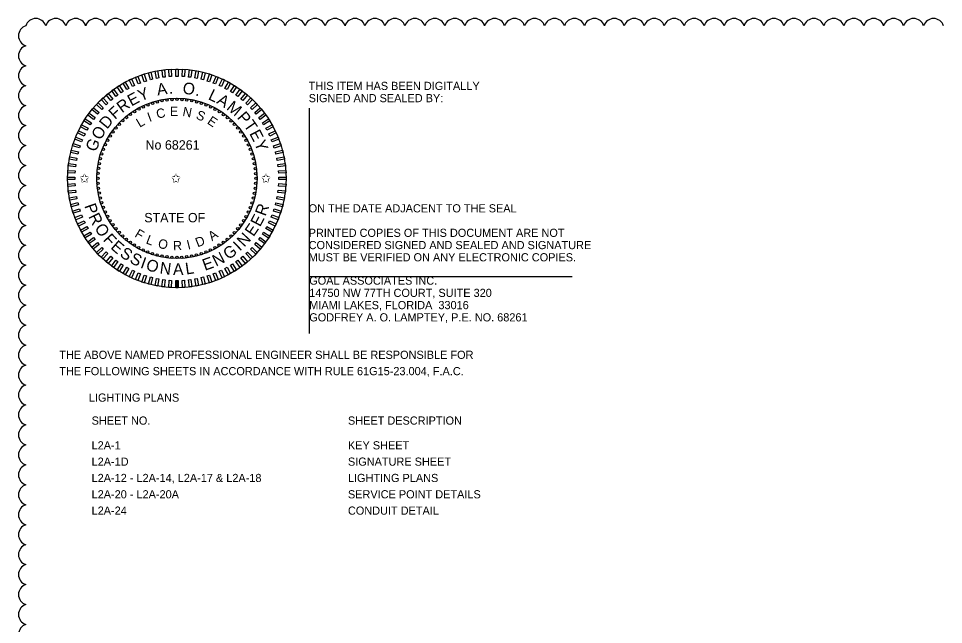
# Model space of a CAD drawing. Extents: x -811 to -790, y -2284 to -2178.
# Drawn here: x -810.85 to -802.91, y -2240.21 to -2235.02 of the extents above; entities that cross this region are included whole.
import ezdxf

# ---------------------------------------------------------------- set-up
doc = ezdxf.new("R2010")
doc.units = 0
for name, color, linetype in [('AdhocPoint_dp', 7, 'Continuous'), ('PlotBorder_dp', 7, 'Continuous'), ('TextMinor', 7, 'Continuous'), ('TextMisc', 7, 'Continuous'), ('TextShtNo', 7, 'Continuous'), ('TextTitle', 7, 'Continuous')]:
    doc.layers.add(name, color=color, linetype=linetype)

msp = doc.modelspace()

# ---------------------------------------------------------------- linework, layer by layer
at = {"layer": 'AdhocPoint_dp'}
for p, q in [((-808.3546, -2235.7843), (-808.3546, -2237.719)), ((-808.3546, -2237.229), (-806.0979, -2237.229))]:
    msp.add_line(p, q, dxfattribs=at)
at = {"layer": 'TextMinor'}
for radius in [0.9375, 0.6875]:
    msp.add_circle((-809.4901, -2236.3877), radius, dxfattribs=at)
at = {"layer": 'TextShtNo'}
for p, q in [((-809.5001, -2237.3253), (-809.5003, -2237.2628)), ((-809.4901, -2237.3252), (-809.4903, -2237.2627)), ((-809.4801, -2237.3252), (-809.4803, -2237.2627))]:
    msp.add_line(p, q, dxfattribs=at)
for points in [[(-809.7508, -2235.5524), (-809.77, -2235.5586), (-809.7893, -2235.4992), (-809.7701, -2235.493)], [(-809.6979, -2235.5377), (-809.7174, -2235.5427), (-809.7329, -2235.4822), (-809.7134, -2235.4772)], [(-809.6441, -2235.5263), (-809.6639, -2235.5301), (-809.6756, -2235.4688), (-809.6558, -2235.465)], [(-809.5897, -2235.5183), (-809.6097, -2235.5209), (-809.6175, -2235.4589), (-809.5975, -2235.4564)], [(-809.5349, -2235.5138), (-809.555, -2235.5151), (-809.559, -2235.4527), (-809.5388, -2235.4515)], [(-809.4799, -2235.5127), (-809.5001, -2235.5127), (-809.5001, -2235.4503), (-809.4799, -2235.4503)], [(-809.425, -2235.5151), (-809.4452, -2235.5138), (-809.4412, -2235.4515), (-809.4211, -2235.4528)], [(-809.3703, -2235.5209), (-809.3904, -2235.5184), (-809.3825, -2235.4564), (-809.3625, -2235.4589)], [(-809.3162, -2235.5301), (-809.336, -2235.5263), (-809.3243, -2235.465), (-809.3045, -2235.4688)], [(-809.2626, -2235.5427), (-809.2822, -2235.5377), (-809.2667, -2235.4772), (-809.2471, -2235.4823)], [(-809.21, -2235.5587), (-809.2292, -2235.5524), (-809.2099, -2235.4931), (-809.1907, -2235.4993)], [(-809.9027, -2235.616), (-809.9204, -2235.6258), (-809.9505, -2235.571), (-809.9328, -2235.5613)], [(-809.8535, -2235.5917), (-809.8717, -2235.6002), (-809.8983, -2235.5438), (-809.8801, -2235.5352)], [(-809.8028, -2235.5704), (-809.8215, -2235.5778), (-809.8445, -2235.5198), (-809.8258, -2235.5124)], [(-809.1585, -2235.5779), (-809.1773, -2235.5705), (-809.1543, -2235.5124), (-809.1355, -2235.5199)], [(-809.1083, -2235.6003), (-809.1266, -2235.5917), (-809.1, -2235.5352), (-809.0817, -2235.5438)], [(-809.0596, -2235.6259), (-809.0773, -2235.6161), (-809.0473, -2235.5614), (-809.0296, -2235.5711)], [(-810.04, -2235.707), (-810.0556, -2235.7199), (-810.0954, -2235.6718), (-810.0798, -2235.6589)], [(-809.9962, -2235.6738), (-810.0125, -2235.6857), (-810.0492, -2235.6352), (-810.0329, -2235.6233)], [(-809.9504, -2235.6435), (-809.9674, -2235.6543), (-810.0009, -2235.6016), (-809.9838, -2235.5908)], [(-809.0127, -2235.6544), (-809.0297, -2235.6436), (-808.9962, -2235.5909), (-808.9792, -2235.6017)], [(-808.9676, -2235.6858), (-808.9839, -2235.674), (-808.9472, -2235.6234), (-808.9308, -2235.6353)], [(-808.9245, -2235.72), (-808.9401, -2235.7071), (-808.9003, -2235.659), (-808.8847, -2235.6719)], [(-810.121, -2235.7813), (-810.1348, -2235.796), (-810.1804, -2235.7533), (-810.1665, -2235.7386)], [(-810.0817, -2235.7429), (-810.0964, -2235.7567), (-810.1392, -2235.7112), (-810.1244, -2235.6974)], [(-808.8837, -2235.7568), (-808.8984, -2235.743), (-808.8557, -2235.6975), (-808.841, -2235.7113)], [(-808.8453, -2235.7962), (-808.8591, -2235.7815), (-808.8136, -2235.7387), (-808.7998, -2235.7534)], [(-810.1579, -2235.8221), (-810.1707, -2235.8377), (-810.2188, -2235.7979), (-810.206, -2235.7823)], [(-808.8094, -2235.8378), (-808.8223, -2235.8223), (-808.7742, -2235.7825), (-808.7613, -2235.798)], [(-810.2235, -2235.9103), (-810.2343, -2235.9273), (-810.287, -2235.8939), (-810.2762, -2235.8768)], [(-810.192, -2235.8652), (-810.2039, -2235.8815), (-810.2544, -2235.8448), (-810.2426, -2235.8285)], [(-808.7762, -2235.8817), (-808.7881, -2235.8653), (-808.7376, -2235.8286), (-808.7257, -2235.845)], [(-808.7459, -2235.9275), (-808.7567, -2235.9104), (-808.7039, -2235.877), (-808.6931, -2235.894)], [(-810.2775, -2236.006), (-810.2861, -2236.0242), (-810.3426, -2235.9976), (-810.334, -2235.9794)], [(-810.252, -2235.9573), (-810.2617, -2235.975), (-810.3164, -2235.9449), (-810.3067, -2235.9272)], [(-808.7184, -2235.9751), (-808.7281, -2235.9574), (-808.6734, -2235.9273), (-808.6637, -2235.945)], [(-808.694, -2236.0244), (-808.7026, -2236.0061), (-808.6461, -2235.9795), (-808.6375, -2235.9978)], [(-810.3, -2236.0562), (-810.3074, -2236.0749), (-810.3654, -2236.0519), (-810.358, -2236.0332)], [(-808.6728, -2236.0751), (-808.6802, -2236.0563), (-808.6222, -2236.0333), (-808.6147, -2236.0521)], [(-810.3192, -2236.1077), (-810.3254, -2236.1269), (-810.3848, -2236.1076), (-810.3786, -2236.0884)], [(-808.6548, -2236.127), (-808.661, -2236.1078), (-808.6016, -2236.0885), (-808.5954, -2236.1077)], [(-810.3477, -2236.2138), (-810.3515, -2236.2336), (-810.4129, -2236.2219), (-810.4091, -2236.2021)], [(-810.3351, -2236.1603), (-810.3401, -2236.1798), (-810.4006, -2236.1643), (-810.3956, -2236.1447)], [(-808.64, -2236.18), (-808.6451, -2236.1604), (-808.5846, -2236.1449), (-808.5796, -2236.1645)], [(-808.6287, -2236.2338), (-808.6325, -2236.214), (-808.5711, -2236.2023), (-808.5673, -2236.2221)], [(-810.357, -2236.268), (-810.3595, -2236.288), (-810.4215, -2236.2802), (-810.4189, -2236.2601)], [(-808.6207, -2236.2882), (-808.6232, -2236.2682), (-808.5613, -2236.2603), (-808.5588, -2236.2804)], [(-810.3652, -2236.3776), (-810.3652, -2236.3977), (-810.4276, -2236.3977), (-810.4276, -2236.3776)], [(-810.3628, -2236.3226), (-810.3641, -2236.3428), (-810.4264, -2236.3389), (-810.4251, -2236.3187)], [(-808.6162, -2236.343), (-808.6174, -2236.3228), (-808.5551, -2236.3189), (-808.5539, -2236.339)], [(-808.6151, -2236.3979), (-808.6151, -2236.3777), (-808.5527, -2236.3777), (-808.5527, -2236.3979)], [(-810.3641, -2236.4325), (-810.3628, -2236.4527), (-810.4251, -2236.4566), (-810.4264, -2236.4364)], [(-808.6175, -2236.4529), (-808.6162, -2236.4327), (-808.5539, -2236.4366), (-808.5551, -2236.4568)], [(-810.3595, -2236.4873), (-810.357, -2236.5073), (-810.4189, -2236.5152), (-810.4215, -2236.4951)], [(-808.6233, -2236.5075), (-808.6207, -2236.4875), (-808.5588, -2236.4953), (-808.5613, -2236.5153)], [(-810.3516, -2236.5417), (-810.3478, -2236.5615), (-810.4091, -2236.5732), (-810.4129, -2236.5534)], [(-810.3402, -2236.5955), (-810.3352, -2236.615), (-810.3957, -2236.6306), (-810.4007, -2236.611)], [(-808.6451, -2236.6152), (-808.6401, -2236.5957), (-808.5796, -2236.6112), (-808.5846, -2236.6307)], [(-808.6325, -2236.5617), (-808.6287, -2236.5419), (-808.5674, -2236.5536), (-808.5712, -2236.5734)], [(-810.3255, -2236.6485), (-810.3192, -2236.6677), (-810.3786, -2236.6869), (-810.3849, -2236.6677)], [(-808.6611, -2236.6678), (-808.6548, -2236.6486), (-808.5954, -2236.6679), (-808.6017, -2236.6871)], [(-810.3075, -2236.7004), (-810.3, -2236.7192), (-810.3581, -2236.7421), (-810.3655, -2236.7234)], [(-810.2862, -2236.7511), (-810.2776, -2236.7694), (-810.3341, -2236.7959), (-810.3427, -2236.7777)], [(-808.7027, -2236.7695), (-808.6941, -2236.7513), (-808.6376, -2236.7778), (-808.6462, -2236.7961)], [(-808.6803, -2236.7193), (-808.6729, -2236.7006), (-808.6148, -2236.7236), (-808.6222, -2236.7423)], [(-810.2618, -2236.8004), (-810.2521, -2236.8181), (-810.3068, -2236.8481), (-810.3165, -2236.8304)], [(-810.2344, -2236.848), (-810.2236, -2236.8651), (-810.2763, -2236.8985), (-810.2871, -2236.8815)], [(-808.7568, -2236.8652), (-808.746, -2236.8482), (-808.6932, -2236.8816), (-808.704, -2236.8987)], [(-808.7282, -2236.8182), (-808.7185, -2236.8005), (-808.6638, -2236.8306), (-808.6735, -2236.8483)], [(-810.204, -2236.8938), (-810.1922, -2236.9102), (-810.2427, -2236.9469), (-810.2545, -2236.9305)], [(-808.7882, -2236.9103), (-808.7763, -2236.894), (-808.7258, -2236.9307), (-808.7377, -2236.947)], [(-810.1708, -2236.9377), (-810.158, -2236.9532), (-810.2061, -2236.993), (-810.2189, -2236.9775)], [(-810.135, -2236.9793), (-810.1211, -2236.994), (-810.1667, -2237.0368), (-810.1805, -2237.0221)], [(-808.8592, -2236.9942), (-808.8454, -2236.9795), (-808.7999, -2237.0222), (-808.8137, -2237.0369)], [(-808.8224, -2236.9534), (-808.8095, -2236.9378), (-808.7614, -2236.9776), (-808.7743, -2236.9932)], [(-810.0965, -2237.0186), (-810.0818, -2237.0325), (-810.1246, -2237.078), (-810.1393, -2237.0642)], [(-810.0557, -2237.0555), (-810.0402, -2237.0683), (-810.08, -2237.1164), (-810.0955, -2237.1036)], [(-810.0127, -2237.0897), (-809.9964, -2237.1015), (-810.0331, -2237.152), (-810.0494, -2237.1402)], [(-808.984, -2237.1016), (-808.9677, -2237.0898), (-808.931, -2237.1403), (-808.9473, -2237.1522)], [(-808.9402, -2237.0685), (-808.9247, -2237.0556), (-808.8848, -2237.1037), (-808.9004, -2237.1166)], [(-808.8985, -2237.0326), (-808.8838, -2237.0188), (-808.8411, -2237.0643), (-808.8558, -2237.0781)], [(-809.9676, -2237.1211), (-809.9505, -2237.1319), (-809.984, -2237.1846), (-810.001, -2237.1738)], [(-809.9206, -2237.1496), (-809.9029, -2237.1594), (-809.933, -2237.2141), (-809.9507, -2237.2043)], [(-809.0775, -2237.1594), (-809.0598, -2237.1497), (-809.0297, -2237.2044), (-809.0474, -2237.2142)], [(-809.0299, -2237.132), (-809.0128, -2237.1212), (-808.9794, -2237.1739), (-808.9964, -2237.1847)], [(-809.8719, -2237.1752), (-809.8536, -2237.1838), (-809.8802, -2237.2402), (-809.8985, -2237.2317)], [(-809.8217, -2237.1976), (-809.8029, -2237.205), (-809.8259, -2237.2631), (-809.8447, -2237.2556)], [(-809.7702, -2237.2168), (-809.751, -2237.223), (-809.7703, -2237.2824), (-809.7895, -2237.2762)], [(-809.7176, -2237.2327), (-809.698, -2237.2378), (-809.7136, -2237.2982), (-809.7331, -2237.2932)], [(-809.6641, -2237.2454), (-809.6443, -2237.2491), (-809.656, -2237.3105), (-809.6758, -2237.3067)], [(-809.3362, -2237.2492), (-809.3163, -2237.2454), (-809.3046, -2237.3067), (-809.3245, -2237.3105)], [(-809.2824, -2237.2378), (-809.2628, -2237.2328), (-809.2473, -2237.2933), (-809.2668, -2237.2983)], [(-809.2294, -2237.2231), (-809.2102, -2237.2169), (-809.1909, -2237.2762), (-809.2101, -2237.2825)], [(-809.1775, -2237.2051), (-809.1587, -2237.1976), (-809.1357, -2237.2557), (-809.1545, -2237.2631)], [(-809.1268, -2237.1838), (-809.1085, -2237.1752), (-809.0819, -2237.2317), (-809.1002, -2237.2403)], [(-809.6099, -2237.2546), (-809.5899, -2237.2571), (-809.5977, -2237.3191), (-809.6177, -2237.3165)], [(-809.5552, -2237.2604), (-809.5351, -2237.2617), (-809.539, -2237.324), (-809.5592, -2237.3227)], [(-809.5003, -2237.2628), (-809.4801, -2237.2628), (-809.4801, -2237.3252), (-809.5003, -2237.3252)], [(-809.4453, -2237.2617), (-809.4252, -2237.2604), (-809.4213, -2237.3227), (-809.4414, -2237.324)], [(-809.3906, -2237.2571), (-809.3705, -2237.2546), (-809.3627, -2237.3166), (-809.3827, -2237.3191)]]:
    msp.add_lwpolyline(points, close=True, dxfattribs=at)
for centre in [(-809.6989, -2235.7433), (-809.6581, -2235.7314), (-809.6165, -2235.7222), (-809.5745, -2235.7155), (-809.5321, -2235.7116), (-809.4896, -2235.7103), (-809.447, -2235.7116), (-809.4047, -2235.7157), (-809.3626, -2235.7224), (-809.3211, -2235.7317), (-809.2802, -2235.7436), (-809.8527, -2235.8154), (-809.816, -2235.7938), (-809.7781, -2235.7745), (-809.739, -2235.7576), (-809.2402, -2235.7581), (-809.2012, -2235.775), (-809.1633, -2235.7943), (-809.1266, -2235.816), (-809.9535, -2235.8935), (-809.9215, -2235.8654), (-809.8879, -2235.8393), (-809.0915, -2235.84), (-809.0579, -2235.8661), (-809.026, -2235.8943), (-810.0379, -2235.9891), (-810.0118, -2235.9555), (-809.9836, -2235.9236), (-808.9959, -2235.9244), (-808.9678, -2235.9563), (-808.9417, -2235.99), (-810.0835, -2236.0609), (-810.0618, -2236.0243), (-808.9178, -2236.0252), (-808.8962, -2236.0619), (-810.1198, -2236.1378), (-810.1029, -2236.0988), (-808.8769, -2236.0998), (-808.86, -2236.1389), (-810.1462, -2236.2187), (-810.1343, -2236.1779), (-808.8456, -2236.1789), (-808.8338, -2236.2198), (-810.1622, -2236.3023), (-810.1555, -2236.2602), (-808.8245, -2236.2614), (-808.8179, -2236.3034), (-810.1676, -2236.3872), (-810.1662, -2236.3446), (-808.814, -2236.3458), (-808.8127, -2236.3883), (-810.1663, -2236.4297), (-808.814, -2236.4308), (-810.1623, -2236.4721), (-810.1557, -2236.5141), (-808.8248, -2236.5152), (-808.8181, -2236.4732), (-810.1464, -2236.5557), (-810.1346, -2236.5966), (-808.846, -2236.5976), (-808.8341, -2236.5568), (-810.1202, -2236.6366), (-810.1034, -2236.6757), (-808.8774, -2236.6767), (-808.8604, -2236.6377), (-810.0841, -2236.7136), (-810.0624, -2236.7503), (-810.0385, -2236.7855), (-808.9424, -2236.7864), (-808.9184, -2236.7512), (-808.8967, -2236.7146), (-810.0125, -2236.8191), (-809.9844, -2236.8511), (-808.9967, -2236.8519), (-808.9685, -2236.82), (-809.9543, -2236.8812), (-809.9224, -2236.9094), (-809.8888, -2236.9355), (-809.0924, -2236.9362), (-809.0587, -2236.9101), (-809.0268, -2236.882), (-809.8536, -2236.9594), (-809.817, -2236.9811), (-809.7791, -2237.0005), (-809.74, -2237.0174), (-809.2413, -2237.0178), (-809.2022, -2237.001), (-809.1642, -2236.9817), (-809.1276, -2236.96), (-809.7, -2237.0319), (-809.6591, -2237.0438), (-809.6176, -2237.0531), (-809.5756, -2237.0598), (-809.5332, -2237.0638), (-809.4901, -2237.0652), (-809.4481, -2237.0639), (-809.4058, -2237.0599), (-809.3637, -2237.0533), (-809.3222, -2237.0441), (-809.2813, -2237.0322)]:
    msp.add_circle(centre, 0.01, dxfattribs=at)
at = {"layer": 'TextTitle'}
for centre, start, end in [((-810.7002, -2235.1062), 17.5, 162.5), ((-810.5291, -2235.1062), 17.5, 162.5), ((-810.358, -2235.1062), 17.5, 162.5), ((-810.1868, -2235.1062), 17.5, 162.5), ((-810.0157, -2235.1062), 17.5, 162.5), ((-809.8446, -2235.1062), 17.5, 162.5), ((-809.6735, -2235.1062), 17.5, 162.5), ((-809.5024, -2235.1062), 17.5, 162.5), ((-809.3312, -2235.1062), 17.5, 162.5), ((-809.1601, -2235.1062), 17.5, 162.5), ((-808.989, -2235.1062), 17.5, 162.5), ((-808.8179, -2235.1062), 17.5, 162.5), ((-808.6467, -2235.1062), 17.5, 162.5), ((-808.4756, -2235.1062), 17.5, 162.5), ((-808.3045, -2235.1062), 17.5, 162.5), ((-808.1334, -2235.1062), 17.5, 162.5), ((-807.9622, -2235.1062), 17.5, 162.5), ((-807.7911, -2235.1062), 17.5, 162.5), ((-807.62, -2235.1062), 17.5, 162.5), ((-807.4489, -2235.1062), 17.5, 162.5), ((-807.2778, -2235.1062), 17.5, 162.5), ((-807.1066, -2235.1062), 17.5, 162.5), ((-806.9355, -2235.1062), 17.5, 162.5), ((-806.7644, -2235.1062), 17.5, 162.5), ((-806.5933, -2235.1062), 17.5, 162.5), ((-806.4221, -2235.1062), 17.5, 162.5), ((-806.251, -2235.1062), 17.5, 162.5), ((-806.0799, -2235.1062), 17.5, 162.5), ((-805.9088, -2235.1062), 17.5, 162.5), ((-805.7377, -2235.1062), 17.5, 162.5), ((-805.5665, -2235.1062), 17.5, 162.5), ((-805.3954, -2235.1062), 17.5, 162.5), ((-805.2243, -2235.1062), 17.5, 162.5), ((-805.0532, -2235.1062), 17.5, 162.5), ((-804.882, -2235.1062), 17.5, 162.5), ((-804.7109, -2235.1062), 17.5, 162.5), ((-804.5398, -2235.1062), 17.5, 162.5), ((-804.3687, -2235.1062), 17.5, 162.5), ((-804.1976, -2235.1062), 17.5, 162.5), ((-804.0264, -2235.1062), 17.5, 162.5), ((-803.8553, -2235.1062), 17.5, 162.5), ((-803.6842, -2235.1062), 17.5, 162.5), ((-803.5131, -2235.1062), 17.5, 162.5), ((-803.3419, -2235.1062), 17.5, 162.5), ((-803.1708, -2235.1062), 17.5, 162.5), ((-802.9997, -2235.1062), 17.5, 162.5), ((-810.7588, -2235.1648), 107.5, 252.5), ((-810.7588, -2235.3359), 107.5, 252.5), ((-810.7588, -2235.507), 107.5, 252.5), ((-810.7588, -2235.6782), 107.5, 252.5), ((-810.7588, -2235.8493), 107.5, 252.5), ((-810.7588, -2236.0204), 107.5, 252.5), ((-810.7588, -2236.1915), 107.5, 252.5), ((-810.7588, -2236.3627), 107.5, 252.5), ((-810.7588, -2236.5338), 107.5, 252.5), ((-810.7588, -2236.7049), 107.5, 252.5), ((-810.7588, -2236.876), 107.5, 252.5), ((-810.7588, -2237.0471), 107.5, 252.5), ((-810.7588, -2237.2183), 107.5, 252.5), ((-810.7588, -2237.3894), 107.5, 252.5), ((-810.7588, -2237.5605), 107.5, 252.5), ((-810.7588, -2237.7316), 107.5, 252.5), ((-810.7588, -2237.9028), 107.5, 252.5), ((-810.7588, -2238.0739), 107.5, 252.5), ((-810.7588, -2238.245), 107.5, 252.5), ((-810.7588, -2238.4161), 107.5, 252.5), ((-810.7588, -2238.5872), 107.5, 252.5), ((-810.7588, -2238.7584), 107.5, 252.5), ((-810.7588, -2238.9295), 107.5, 252.5), ((-810.7588, -2239.1006), 107.5, 252.5), ((-810.7588, -2239.2717), 107.5, 252.5), ((-810.7588, -2239.4429), 107.5, 252.5), ((-810.7588, -2239.614), 107.5, 252.5), ((-810.7588, -2239.7851), 107.5, 252.5), ((-810.7588, -2239.9562), 107.5, 252.5), ((-810.7588, -2240.1273), 107.5, 252.5), ((-810.7588, -2240.2985), 107.5, 252.5)]:
    msp.add_arc(centre, 0.0897, start, end, dxfattribs=at)

# ---------------------------------------------------------------- texts
at = {"layer": 'PlotBorder_dp'}
for s, p in [('THIS ITEM HAS BEEN DIGITALLY', (-808.3596, -2235.6292)), ('SIGNED AND SEALED BY:', (-808.3596, -2235.7342)), ('ON THE DATE ADJACENT TO THE SEAL', (-808.3596, -2236.6792)), ('PRINTED COPIES OF THIS DOCUMENT ARE NOT ', (-808.3596, -2236.8892)), ('CONSIDERED SIGNED AND SEALED AND SIGNATURE ', (-808.3596, -2236.9942)), ('MUST BE VERIFIED ON ANY ELECTRONIC COPIES.', (-808.3596, -2237.0992)), ('GOAL ASSOCIATES INC.', (-808.3546, -2237.299)), ('14750 NW 77TH COURT, SUITE 320', (-808.3546, -2237.404)), ('MIAMI LAKES, FLORIDA  33016', (-808.3546, -2237.509)), ('GODFREY A. O. LAMPTEY, P.E. NO. 68261', (-808.3546, -2237.614)), ('THE ABOVE NAMED PROFESSIONAL ENGINEER SHALL BE RESPONSIBLE FOR ', (-810.4987, -2237.9352)), ('THE FOLLOWING SHEETS IN ACCORDANCE WITH RULE 61G15-23.004, F.A.C.', (-810.4987, -2238.0752)), ('LIGHTING PLANS', (-810.245, -2238.3022))]:
    msp.add_text(s, height=0.07, dxfattribs=at).set_placement(p)
at = {"layer": 'TextMisc'}
for s, p in [('SHEET NO.', (-810.2215, -2238.4992)), ('SHEET DESCRIPTION', (-808.0226, -2238.4992)), ('L2A-1', (-810.2215, -2238.7114)), ('KEY SHEET', (-808.0226, -2238.7114)), ('L2A-1D', (-810.2215, -2238.8514)), ('SIGNATURE SHEET', (-808.0226, -2238.8514)), ('L2A-12 - L2A-14, L2A-17 & L2A-18', (-810.2215, -2238.9914)), ('LIGHTING PLANS', (-808.0226, -2238.9914)), ('L2A-20 - L2A-20A', (-810.2215, -2239.1314)), ('SERVICE POINT DETAILS', (-808.0226, -2239.1314)), ('L2A-24', (-810.2215, -2239.2714)), ('CONDUIT DETAIL', (-808.0226, -2239.2714))]:
    msp.add_text(s, height=0.07, dxfattribs=at).set_placement(p)
at = {"layer": 'TextShtNo'}
for s, height, rotation, p in [('A', 0.1, 8.80884, (-809.6551, -2235.6771)), ('O', 0.1, 352.18771, (-809.4449, -2235.6596)), ('E', 0.1, 28.10553, (-809.8806, -2235.7716)), ('Y', 0.1, 21.06329, (-809.8021, -2235.7283)), ('.', 0.1, 1.04184, (-809.5575, -2235.6613)), ('.', 0.1, 343.52684, (-809.3358, -2235.6747)), ('L', 0.1, 334.67271, (-809.2279, -2235.707)), ('R', 0.1, 35.92688, (-809.9609, -2235.8304)), ('A', 0.1, 328.40959, (-809.1552, -2235.7397)), ('M', 0.1, 320.6426, (-809.0707, -2235.7909)), ('F', 0.1, 42.37723, (-810.0205, -2235.8868)), ('I', 0.08, 20.01168, (-809.7258, -2235.9037)), ('C', 0.08, 12.20255, (-809.6579, -2235.8761)), ('E', 0.08, 0.41861, (-809.5498, -2235.8527)), ('N', 0.08, 349.29143, (-809.4455, -2235.8512)), ('S', 0.08, 337.02207, (-809.3325, -2235.8729)), ('P', 0.1, 311.19658, (-808.9784, -2235.8678)), ('D', 0.1, 50.8569, (-810.0886, -2235.9705)), ('L', 0.08, 30.40215, (-809.8093, -2235.9541)), ('E', 0.08, 325.86633, (-809.2358, -2235.9132)), ('T', 0.1, 304.45632, (-808.9209, -2235.9315)), ('O', 0.1, 59.51777, (-810.1446, -2236.0654)), ('E', 0.1, 297.63152, (-808.8707, -2236.0023)), ('G', 0.1, 68.0518, (-810.1851, -2236.1661)), ('Y', 0.1, 290.58928, (-808.8281, -2236.0812)), ('P', 0.1, 289.40551, (-810.2848, -2236.6223)), ('R', 0.1, 69.5134, (-808.7299, -2236.7174)), ('R', 0.1, 296.14576, (-810.2518, -2236.714)), ('E', 0.1, 62.47116, (-808.7761, -2236.8082)), ('E', 0.1, 55.42892, (-808.833, -2236.8925)), ('O', 0.1, 303.96711, (-810.2003, -2236.8146)), ('F', 0.1, 312.62798, (-810.1279, -2236.9167)), ('F', 0.08, 328.72408, (-809.8582, -2236.8843)), ('A', 0.08, 34.49917, (-809.1883, -2236.9271)), ('N', 0.1, 47.17876, (-808.9123, -2236.9816)), ('E', 0.1, 319.07833, (-810.0645, -2236.985)), ('L', 0.08, 339.29159, (-809.7609, -2236.9434)), ('O', 0.08, 349.68206, (-809.6562, -2236.9831)), ('R', 0.08, 2.33977, (-809.5217, -2237.005)), ('I', 0.08, 14.20366, (-809.3941, -2236.9984)), ('D', 0.08, 22.01279, (-809.312, -2236.9796)), ('I', 0.1, 43.64556, (-808.9499, -2237.0161)), ('S', 0.1, 326.12056, (-809.9869, -2237.0509)), ('G', 0.1, 35.11153, (-809.0492, -2237.0893)), ('S', 0.1, 333.193, (-809.9015, -2237.107)), ('I', 0.1, 340.26543, (-809.8098, -2237.1522)), ('O', 0.1, 343.79863, (-809.7621, -2237.1704)), ('E', 0.1, 19.81912, (-809.2498, -2237.1807)), ('N', 0.1, 26.86136, (-809.1544, -2237.1453)), ('N', 0.1, 352.45949, (-809.6411, -2237.2025)), ('A', 0.1, 0.70966, (-809.5227, -2237.2157)), ('L', 0.1, 8.47665, (-809.4105, -2237.2125))]:
    msp.add_text(s, height=height, rotation=rotation, dxfattribs=at).set_placement(p)
for s, p in [('No 68261', (-809.7591, -2236.1405)), ('✩', (-810.3251, -2236.4257)), ('✩', (-809.5404, -2236.4257)), ('✩', (-808.7685, -2236.4257)), ('STATE OF', (-809.7698, -2236.7639))]:
    msp.add_text(s, height=0.08, dxfattribs=at).set_placement(p)

doc.saveas('drawing.dxf')
